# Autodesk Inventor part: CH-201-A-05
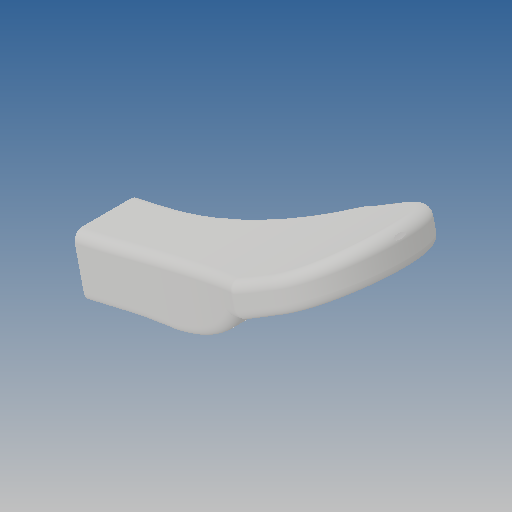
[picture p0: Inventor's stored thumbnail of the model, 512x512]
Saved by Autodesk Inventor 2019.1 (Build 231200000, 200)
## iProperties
Created: 2012-09
Part Number: CH-201-A-05
Material: Ogólny
Document SubType Name: Modeling
Designer: CADENGINEERING4
Density: 1 g/cm^3
Appearance: Domyślna
Author: CADENGINEERING4
Revision Number: ÈÎºÎ
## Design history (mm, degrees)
feature "³é¿Ç2"
node "Bryła1"
